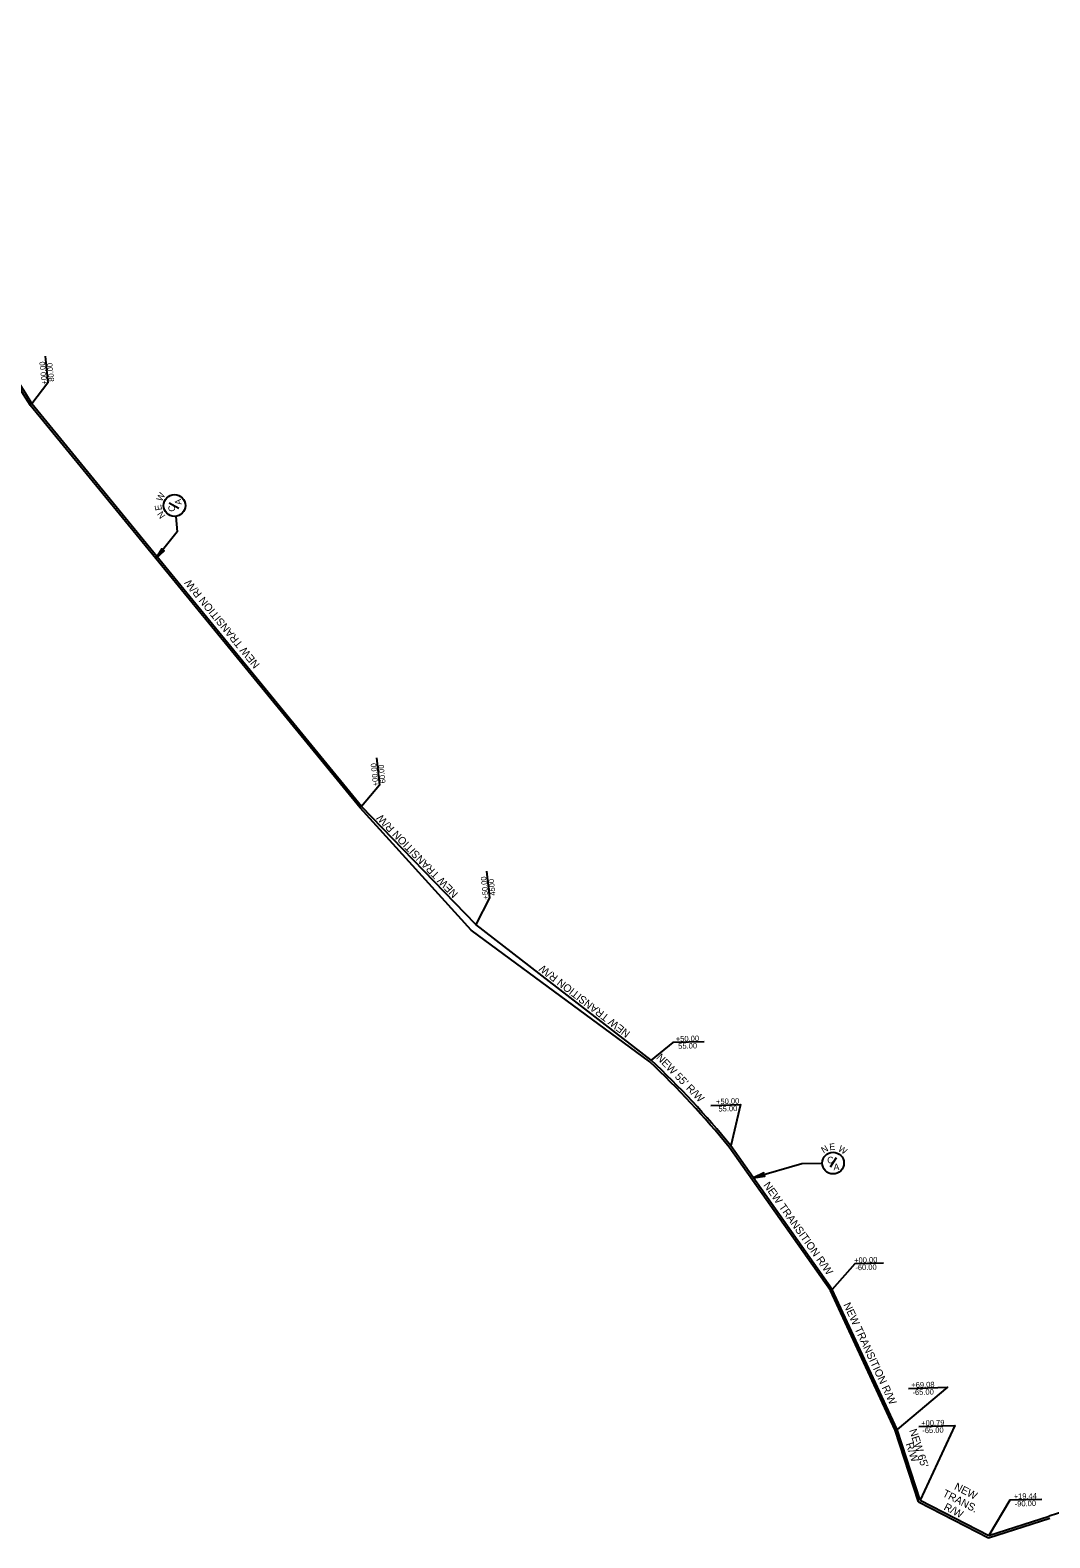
# Model space of a CAD drawing. Extents: x 2003184 to 2010449, y 855784 to 861212.
# Drawn here: x 2004778 to 2005713, y 858181 to 859563 of the extents above; entities that cross this region are included whole.
import ezdxf

# ---------------------------------------------------------------- set-up
doc = ezdxf.new("R2010")
doc.units = 0
for name, color, linetype in [('RD_PD_Control_Access', 7, 'Continuous'), ('RD_PD_RW', 7, 'Continuous'), ('RD_PD_RW_TX', 7, 'Continuous')]:
    doc.layers.add(name, color=color, linetype=linetype)

msp = doc.modelspace()

# ---------------------------------------------------------------- linework, layer by layer
at = {"layer": 'RD_PD_Control_Access'}
for p, q in [((2005080.8, 858850), (2004778.4, 859219.2)), ((2004905.8, 859129.5), (2004914.7, 859124.8)), ((2005182.6, 858737.7), (2005080.8, 858850)), ((2005346.5, 858617.1), (2005182.6, 858737.7)), ((2005512.1, 858407.5), (2005419.2, 858539)), ((2005517.3, 858529.1), (2005511.9, 858520.6)), ((2005571.5, 858279.3), (2005512.1, 858407.5)), ((2005592.7, 858213.7), (2005571.5, 858279.3)), ((2005592.7, 858213.7), (2005657.1, 858180.7)), ((2005657.1, 858180.7), (2005713.3, 858198.8))]:
    msp.add_line(p, q, dxfattribs=at)
for points in [[(2004911.8, 859117.1), (2004913.3, 859103.1), (2004893.6, 859078.5)], [(2005504.5, 858524), (2005485.8, 858523.5), (2005441.5, 858510.9)]]:
    msp.add_lwpolyline(points, dxfattribs=at)
for points in [[(2004893.6, 859078.5), (2004901.3, 859085.7), (2004899.1, 859085.4), (2004899, 859087.5)], [(2005441.5, 858510.9), (2005451.9, 858512.3), (2005449.9, 858513.3), (2005451.1, 858515.2)]]:
    msp.add_lwpolyline(points, close=True, dxfattribs=at)
for centre in [(2004910.7, 859127.1), (2005514.5, 858524.3)]:
    msp.add_circle(centre, 10, dxfattribs=at)
for centre, radius, start, end in [((2006028, 860016), 1482, 197.8169, 212.5217), ((2004790.2, 858027), 811, 39.1479, 46.6933)]:
    msp.add_arc(centre, radius, start, end, dxfattribs=at)
at = {"layer": 'RD_PD_RW'}
for p, q in [((2005082.3, 858851.3), (2004780, 859220.4)), ((2005187.1, 858743), (2005082.3, 858851.3)), ((2005347.8, 858618.7), (2005187.1, 858743)), ((2005513.8, 858408.5), (2005420.8, 858540.2)), ((2005573.4, 858280), (2005513.8, 858408.5)), ((2005594.4, 858215.1), (2005573.4, 858280)), ((2005594.4, 858215.1), (2005657.3, 858182.9)), ((2005657.3, 858182.9), (2005712.6, 858200.7))]:
    msp.add_line(p, q, dxfattribs=at)
for centre, radius, start, end in [((2006028, 860016), 1480, 197.8259, 212.5171), ((2004790.2, 858027), 813, 39.1431, 46.7019), ((2006059.8, 857126.4), 1129, 94.8168, 107.9087)]:
    msp.add_arc(centre, radius, start, end, dxfattribs=at)
at = {"layer": 'RD_PD_RW_TX'}
for points in [[(2004792.1, 859264), (2004794.7, 859239.6), (2004780, 859220.4)], [(2005096, 858895.8), (2005098.7, 858870.6), (2005082.3, 858851.3)], [(2005196.8, 858791.9), (2005199.4, 858767.5), (2005187.1, 858743)], [(2005396.2, 858635.5), (2005367.5, 858634.7), (2005347.8, 858618.7)], [(2005402.5, 858577.2), (2005429.7, 858577.9), (2005420.8, 858540.2)], [(2005560.8, 858432.6), (2005534.6, 858431.9), (2005513.8, 858408.5)], [(2005583.7, 858317.7), (2005619.3, 858318.7), (2005573.4, 858280)], [(2005593.3, 858282.8), (2005626.1, 858283.6), (2005594.4, 858215.1)], [(2005705.9, 858216), (2005676.6, 858215.2), (2005657.3, 858182.9)]]:
    msp.add_lwpolyline(points, dxfattribs=at)

# ---------------------------------------------------------------- texts
at = {"layer": 'RD_PD_Control_Access'}
for s, rotation, p in [('W', 62.6413, (2004899, 859130.3)), ('E', 100.3188, (2004899.3, 859123.1)), ('N', 125.4371, (2004902.7, 859117.8)), ('C', 96.1251, (2004911.5, 859121.8)), ('A', 96.1251, (2004917.3, 859128.1)), ('E', 5.803, (2005511.4, 858536)), ('N', 30.9213, (2005505.8, 858533)), ('C', 1.6093, (2005509.2, 858524)), ('W', 328.1255, (2005518.6, 858535.8)), ('A', 1.6093, (2005515, 858517.7))]:
    msp.add_text(s, height=6, rotation=rotation, dxfattribs=at).set_placement(p)
at = {"layer": 'RD_PD_RW_TX'}
for s, height, rotation, p in [('+00.00', 5, 96.1251, (2004794, 859238.2)), ('80.00', 5, 96.1251, (2004800.5, 859240.9)), ('NEW TRANSITION R/W', 7, 129.314, (2004989.3, 858981.4)), ('+00.00', 5, 96.1251, (2005097.8, 858870)), ('60.00', 5, 96.1251, (2005104.3, 858872.7)), ('NEW TRANSITION R/W', 7, 134.0687, (2005171.2, 858771.5)), ('+50.00', 5, 96.1251, (2005198.7, 858766.1)), ('4500', 5, 96.1251, (2005205.1, 858769.7)), ('NEW TRANSITION R/W', 7, 142.2701, (2005329.1, 858644.2)), ('+50.00', 5, 1.6093, (2005370.4, 858635.6)), ("NEW 55' R/W", 7, 314.3463, (2005351.9, 858620.5)), ('55.00', 5, 1.6093, (2005372.6, 858629)), ('+50.00', 5, 1.6093, (2005407.3, 858578.2)), ('55.00', 5, 1.6093, (2005409.5, 858571.5)), ('NEW TRANSITION R/W', 7, 305.3577, (2005450.3, 858504)), ('+00.00', 5, 1.6093, (2005533.9, 858432.7)), ('-60.00', 5, 1.6093, (2005535, 858426)), ('NEW TRANSITION R/W', 7, 294.8724, (2005523.8, 858394.5)), ('+69.08', 5, 1.6093, (2005586.3, 858318.3)), ('-65.00', 5, 1.6093, (2005587.4, 858311.6)), ("NEW 65' ", 7, 287.9087, (2005584.3, 858279.3)), ('+00.79', 5, 1.6093, (2005595.4, 858283.3)), ('-65.00', 5, 1.6093, (2005596.4, 858276.6)), ('R/W', 7, 287.9087, (2005581, 858266.9)), ('TRANS. ', 7, 332.9087, (2005614.3, 858219.2)), ('NEW', 7, 332.9087, (2005625, 858225.5)), ('R/W', 7, 332.9087, (2005615.4, 858206.8)), ('+19.44', 5, 1.6093, (2005680.2, 858216.2)), ('-90.00', 5, 1.6093, (2005681.1, 858209.4))]:
    msp.add_text(s, height=height, rotation=rotation, dxfattribs=at).set_placement(p)

doc.saveas('drawing.dxf')
